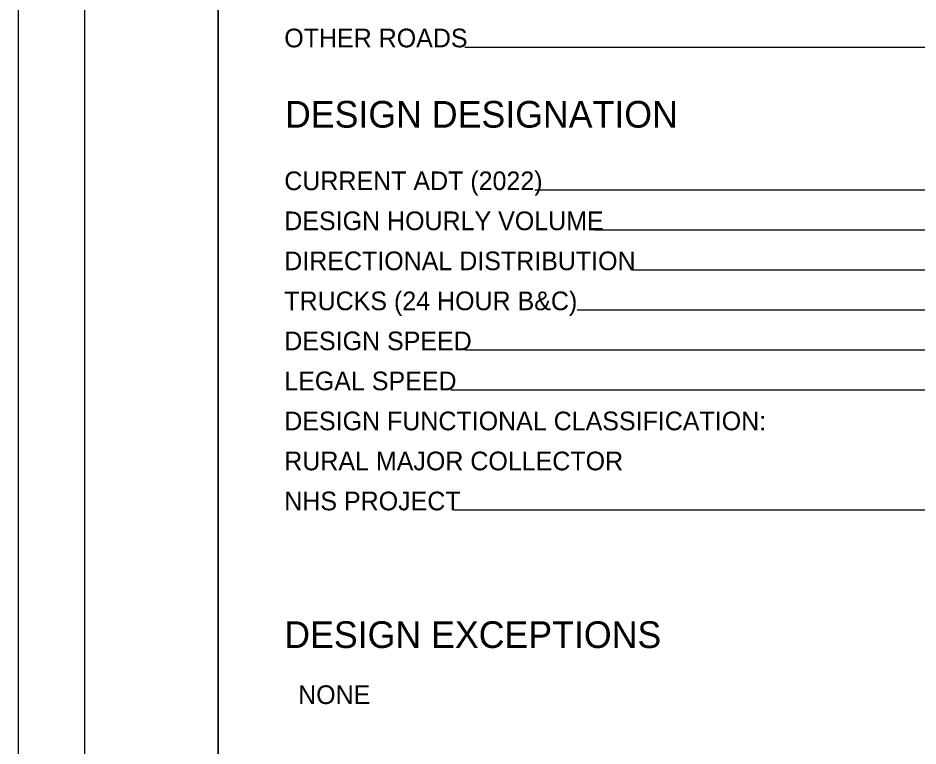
# Model space of a CAD drawing. Extents: x 0 to 34, y 0 to 22.
# Drawn here: x 0 to 6.74, y 5.64 to 11.1 of the extents above; entities that cross this region are included whole.
import ezdxf

# ---------------------------------------------------------------- set-up
doc = ezdxf.new("R2010")
doc.units = 0
for name, color, linetype in [('SH_Border', 7, 'Continuous'), ('SH_Cut_Line', 7, 'Continuous'), ('SH_Data', 7, 'Continuous'), ('SH_Text', 7, 'Continuous')]:
    doc.layers.add(name, color=color, linetype=linetype)

msp = doc.modelspace()

# ---------------------------------------------------------------- linework, layer by layer
at = {"layer": 'SH_Border'}
for points in [[(0.5, 21.5), (1.5, 21.5), (1.5, 0.5), (0.5, 0.5)], [(1.5, 21.5), (33.5, 21.5), (33.5, 0.5), (1.5, 0.5)]]:
    msp.add_lwpolyline(points, close=True, dxfattribs=at)
at = {"layer": 'SH_Cut_Line'}
msp.add_lwpolyline([(0, 0), (34, 0), (34, 22), (0, 22)], close=True, dxfattribs=at)
at = {"layer": 'SH_Data'}
for p, q in [((7.7, 10.8767), (3.3471, 10.8767)), ((7.6424, 9.8062), (3.871, 9.8062)), ((7.6368, 9.5062), (4.3185, 9.5062)), ((7.6368, 9.2062), (4.6037, 9.2062)), ((7.6368, 8.9062), (4.1885, 8.9062)), ((7.6368, 8.6062), (3.346, 8.6062)), ((7.6368, 8.3062), (3.2422, 8.3062)), ((7.6368, 7.4062), (3.2669, 7.4062))]:
    msp.add_line(p, q, dxfattribs=at)

# ---------------------------------------------------------------- texts
msp.add_text('DESIGN DESIGNATION', height=0.2, dxfattribs=at).set_placement((2, 10.2747))
at = {"layer": 'SH_Text'}
for s, height, p in [('OTHER ROADS', 0.14, (1.9944, 10.8767)), ('CURRENT ADT (2022)', 0.14, (1.9944, 9.8062)), ('DESIGN HOURLY VOLUME', 0.14, (1.9944, 9.5062)), ('DIRECTIONAL DISTRIBUTION', 0.14, (1.9944, 9.2062)), ('TRUCKS (24 HOUR B&C)', 0.14, (1.9944, 8.9062)), ('DESIGN SPEED', 0.14, (1.9944, 8.6062)), ('LEGAL SPEED', 0.14, (1.9944, 8.3062)), ('DESIGN FUNCTIONAL CLASSIFICATION:', 0.14, (1.9944, 8.0062)), ('RURAL MAJOR COLLECTOR', 0.14, (1.9944, 7.7062)), ('NHS PROJECT', 0.14, (1.9944, 7.4062)), ('DESIGN EXCEPTIONS', 0.2, (1.9944, 6.3744)), ('  NONE', 0.14, (1.9944, 5.9544))]:
    msp.add_text(s, height=height, dxfattribs=at).set_placement(p)

doc.saveas('drawing.dxf')
